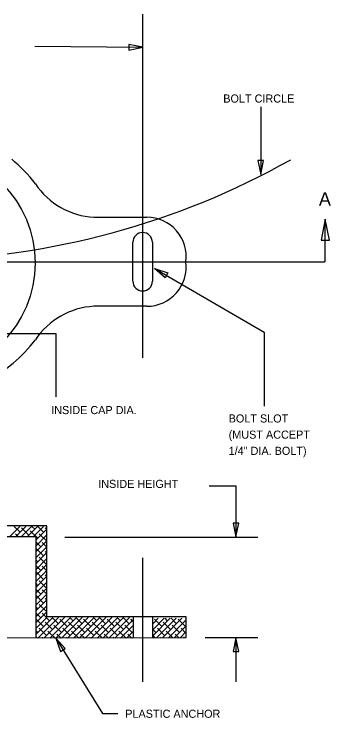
# Model space of a CAD drawing. Extents: x 12.4 to 19.6, y 6 to 16.1.
# Drawn here: x 16.63 to 18.97, y 10.68 to 15.9 of the extents above; entities that cross this region are included whole.
import ezdxf

# ---------------------------------------------------------------- set-up
doc = ezdxf.new("R2010")
doc.units = 0
for name, color, linetype in [('DETL-DIMS', 7, 'Continuous'), ('DETL-LINE', 7, 'Continuous'), ('DETL-NOTE', 7, 'Continuous'), ('DETL-PATT', 7, 'Continuous')]:
    doc.layers.add(name, color=color, linetype=linetype)

msp = doc.modelspace()

# ---------------------------------------------------------------- linework, layer by layer
at = {"layer": 'DETL-DIMS'}
for p, q in [((17.5789, 13.3479), (17.5789, 15.8959)), ((16.7799, 15.6569), (17.5759, 15.6499)), ((18.4529, 15.2089), (18.4529, 14.7269)), ((17.6869, 13.9969), (18.4779, 13.5379)), ((16.9369, 13.5269), (16.0979, 13.5269)), ((16.9369, 13.0579), (16.9369, 13.5269)), ((18.4779, 13.5379), (18.4779, 12.9899)), ((18.0699, 12.3989), (18.2669, 12.3989)), ((18.2669, 12.3989), (18.2669, 12.0199)), ((17.0019, 12.0199), (18.4299, 12.0199)), ((17.5769, 11.8669), (17.5769, 10.9479)), ((16.9339, 11.2709), (17.2801, 10.7133)), ((18.0419, 11.2749), (18.4299, 11.2749)), ((18.2669, 11.2749), (18.2669, 10.9479)), ((17.2801, 10.7133), (17.3931, 10.7133))]:
    msp.add_line(p, q, dxfattribs=at)
for points in [[(17.5789, 15.6499), (17.4749, 15.6699), (17.4749, 15.6289)], [(18.4519, 14.7079), (18.4729, 14.8109), (18.4309, 14.8109)], [(18.9289, 14.3759), (18.8989, 14.2209), (18.9609, 14.2209)], [(17.6659, 14.0099), (17.7649, 13.9769), (17.7449, 13.9409)], [(18.2689, 12.0209), (18.2899, 12.1239), (18.2489, 12.1239)], [(16.9339, 11.2709), (16.9699, 11.1723), (17.0051, 11.1935)], [(18.2679, 11.2739), (18.2479, 11.1709), (18.2889, 11.1709)]]:
    msp.add_lwpolyline(points, close=True, dxfattribs=at)
for points in [[(18.9289, 14.0599), (18.9289, 14.3759)], [(12.9759, 14.0599), (18.9259, 14.0599)]]:
    msp.add_lwpolyline(points, dxfattribs=at)
msp.add_arc((15.8374, 19.8541), 5.7813, 243.01004, 299.38525, dxfattribs=at)
at = {"layer": 'DETL-LINE'}
for points in [[(17.2169, 14.3899), (17.6089, 14.3899)], [(17.5059, 14.0599), (17.5059, 14.2049)], [(17.6499, 14.2049), (17.6499, 14.0599), (17.6499, 13.9159)], [(17.5059, 13.9159), (17.5059, 14.0599)], [(17.6089, 13.7299), (17.2169, 13.7299)], [(16.2019, 11.2739), (17.8999, 11.2749), (17.8999, 11.4279), (16.8679, 11.4279), (16.8679, 12.1019), (15.0529, 12.1019), (15.0529, 11.4179), (13.9819, 11.4179), (13.9809, 11.2729)], [(15.1359, 11.2799), (15.1359, 12.0229), (16.7859, 12.0229), (16.7859, 11.2799)], [(17.5079, 11.4279), (17.5079, 11.2749)], [(17.6519, 11.4279), (17.6519, 11.2749)]]:
    msp.add_lwpolyline(points, dxfattribs=at)
msp.add_circle((15.952, 14.0508), 0.83, dxfattribs=at)
for centre, radius, start, end in [((15.9586, 14.0188), 1.0313, 36.8699, 50.9692), ((17.248, 14.9475), 0.5583, 213.721, 266.7892), ((17.6086, 14.0987), 0.2913, 352.3718, 90), ((17.5776, 14.2044), 0.0722, 0, 180), ((17.6086, 14.0214), 0.2913, 270, 7.6282), ((17.5776, 13.9157), 0.0722, 180, 0), ((17.248, 13.1726), 0.5583, 93.2108, 146.279), ((15.9586, 14.1013), 1.0313, 270, 323.1301)]:
    msp.add_arc(centre, radius, start, end, dxfattribs=at)
at = {"layer": 'DETL-PATT'}
for p, q in [((16.5889, 12.0189), (16.6679, 12.0989)), ((16.6699, 12.0559), (16.6269, 12.0989)), ((16.6329, 12.0189), (16.7119, 12.0989)), ((16.6769, 12.0189), (16.7559, 12.0989)), ((16.7349, 12.0339), (16.6799, 12.0889)), ((16.7199, 12.0189), (16.7999, 12.0989)), ((16.8009, 12.0119), (16.7459, 12.0669)), ((16.7789, 12.0779), (16.7579, 12.0989)), ((16.7639, 12.0189), (16.8439, 12.0989)), ((16.7859, 11.9969), (16.8649, 12.0769)), ((16.8439, 12.0559), (16.8019, 12.0989)), ((16.8649, 12.0789), (16.8549, 12.0889)), ((16.6619, 12.0189), (16.6369, 12.0449)), ((16.7059, 12.0189), (16.7019, 12.0229)), ((16.7859, 11.9529), (16.8649, 12.0329)), ((16.8649, 11.9919), (16.8119, 12.0449)), ((16.7859, 11.9099), (16.8649, 11.9889)), ((16.8229, 11.9469), (16.7859, 11.9839)), ((16.8649, 11.9479), (16.8339, 11.9799)), ((16.7859, 11.8659), (16.8649, 11.9449)), ((16.7859, 11.8219), (16.8649, 11.9019)), ((16.8439, 11.8809), (16.7899, 11.9359)), ((16.8649, 11.9039), (16.8549, 11.9139)), ((16.7859, 11.7779), (16.8649, 11.8579)), ((16.8009, 11.8369), (16.7859, 11.8519)), ((16.8649, 11.8169), (16.8119, 11.8699)), ((16.7859, 11.7349), (16.8649, 11.8139)), ((16.8229, 11.7719), (16.7859, 11.8089)), ((16.8649, 11.7729), (16.8339, 11.8049)), ((16.7859, 11.6909), (16.8649, 11.7699)), ((16.8439, 11.7059), (16.7899, 11.7609)), ((16.8649, 11.7289), (16.8549, 11.7389)), ((16.7859, 11.6469), (16.8649, 11.7269)), ((16.8649, 11.6419), (16.8119, 11.6949)), ((16.7859, 11.6029), (16.8649, 11.6829)), ((16.8009, 11.6619), (16.7859, 11.6769)), ((16.7859, 11.5599), (16.8649, 11.6389)), ((16.8229, 11.5969), (16.7859, 11.6339)), ((16.7859, 11.5159), (16.8649, 11.5949)), ((16.8439, 11.5309), (16.7899, 11.5859)), ((16.8649, 11.5979), (16.8339, 11.6299)), ((16.7859, 11.4719), (16.8649, 11.5519)), ((16.8649, 11.5539), (16.8549, 11.5639)), ((16.7859, 11.4279), (16.8649, 11.5079)), ((16.8009, 11.4869), (16.7859, 11.5019)), ((16.8649, 11.4669), (16.8119, 11.5199)), ((16.7859, 11.3849), (16.8649, 11.4639)), ((16.8229, 11.4219), (16.7859, 11.4589)), ((16.8879, 11.3999), (16.8339, 11.4549)), ((16.7859, 11.3409), (16.8689, 11.4239)), ((16.7859, 11.2969), (16.9119, 11.4239)), ((16.8439, 11.3559), (16.7899, 11.4109)), ((16.8029, 11.2709), (16.9559, 11.4239)), ((16.8469, 11.2709), (16.9999, 11.4239)), ((16.9099, 11.3339), (16.8549, 11.3889)), ((16.8899, 11.2709), (17.0439, 11.4239)), ((16.9539, 11.3779), (16.9079, 11.4239)), ((16.9339, 11.2709), (17.0869, 11.4239)), ((17.0189, 11.3559), (16.9649, 11.4109)), ((16.9779, 11.2709), (17.1309, 11.4239)), ((16.9979, 11.4219), (16.9949, 11.4239)), ((17.0219, 11.2709), (17.1749, 11.4239)), ((17.0849, 11.3339), (17.0299, 11.3889)), ((17.0629, 11.3999), (17.0389, 11.4239)), ((17.0649, 11.2709), (17.2189, 11.4239)), ((17.1289, 11.3779), (17.0829, 11.4239)), ((17.1089, 11.2709), (17.2619, 11.4239)), ((17.1939, 11.3559), (17.1399, 11.4109)), ((17.1529, 11.2709), (17.3059, 11.4239)), ((17.1729, 11.4219), (17.1699, 11.4239)), ((17.1969, 11.2709), (17.3499, 11.4239)), ((17.2599, 11.3339), (17.2049, 11.3889)), ((17.2379, 11.3999), (17.2139, 11.4239)), ((17.2399, 11.2709), (17.3939, 11.4239)), ((17.3039, 11.3779), (17.2579, 11.4239)), ((17.2839, 11.2709), (17.4369, 11.4239)), ((17.3699, 11.3559), (17.3149, 11.4109)), ((17.3279, 11.2709), (17.4809, 11.4239)), ((17.3479, 11.4219), (17.3449, 11.4239)), ((17.3719, 11.2709), (17.5049, 11.4049)), ((17.4349, 11.3339), (17.3799, 11.3889)), ((17.4129, 11.3999), (17.3889, 11.4239)), ((17.4789, 11.3779), (17.4329, 11.4239)), ((17.5049, 11.3949), (17.4899, 11.4109)), ((17.6529, 11.2889), (17.7819, 11.4179)), ((17.6529, 11.3329), (17.7379, 11.4179)), ((17.6529, 11.3769), (17.6939, 11.4179)), ((17.6539, 11.3779), (17.6529, 11.3789)), ((17.7189, 11.3559), (17.6649, 11.4109)), ((17.6839, 11.2759), (17.8249, 11.4179)), ((17.7269, 11.2759), (17.8689, 11.4179)), ((17.7849, 11.3339), (17.7299, 11.3889)), ((17.7629, 11.3999), (17.7449, 11.4179)), ((17.7709, 11.2759), (17.8959, 11.4019)), ((17.8289, 11.3779), (17.7889, 11.4179)), ((17.8949, 11.3559), (17.8399, 11.4109)), ((16.8009, 11.3119), (16.7859, 11.3279)), ((16.8659, 11.2899), (16.8119, 11.3449)), ((16.9299, 11.2709), (16.8769, 11.3229)), ((16.9759, 11.3119), (16.9209, 11.3669)), ((17.0409, 11.2899), (16.9869, 11.3449)), ((17.1049, 11.2709), (17.0519, 11.3229)), ((17.1509, 11.3119), (17.0959, 11.3669)), ((17.2159, 11.2899), (17.1619, 11.3449)), ((17.2799, 11.2709), (17.2269, 11.3229)), ((17.3259, 11.3119), (17.2709, 11.3669)), ((17.3909, 11.2899), (17.3369, 11.3449)), ((17.4549, 11.2709), (17.4019, 11.3229)), ((17.4149, 11.2709), (17.5049, 11.3609)), ((17.5009, 11.3119), (17.4459, 11.3669)), ((17.6759, 11.3119), (17.6529, 11.3349)), ((17.7409, 11.2899), (17.6869, 11.3449)), ((17.7989, 11.2759), (17.7519, 11.3229)), ((17.8509, 11.3119), (17.7959, 11.3669)), ((17.8149, 11.2759), (17.8959, 11.3579)), ((17.8959, 11.3099), (17.8619, 11.3449)), ((16.7989, 11.2709), (16.7859, 11.2839)), ((16.8419, 11.2709), (16.8339, 11.2789)), ((16.9739, 11.2709), (16.9429, 11.3009)), ((17.0169, 11.2709), (17.0089, 11.2789)), ((17.1489, 11.2709), (17.1179, 11.3009)), ((17.1919, 11.2709), (17.1839, 11.2789)), ((17.3239, 11.2709), (17.2929, 11.3009)), ((17.3669, 11.2709), (17.3589, 11.2789)), ((17.4589, 11.2709), (17.5049, 11.3169)), ((17.4989, 11.2709), (17.4679, 11.3009)), ((17.5029, 11.2709), (17.5049, 11.2729)), ((17.6679, 11.2759), (17.6529, 11.2919)), ((17.7119, 11.2759), (17.7089, 11.2789)), ((17.8429, 11.2759), (17.8179, 11.3009)), ((17.8589, 11.2759), (17.8959, 11.3139)), ((17.8869, 11.2759), (17.8839, 11.2789))]:
    msp.add_line(p, q, dxfattribs=at)

# ---------------------------------------------------------------- texts
at = {"layer": 'DETL-NOTE'}
for s, height, p in [('BOLT CIRCLE', 0.06, (18.1749, 15.2399)), ('A', 0.1, (18.8829, 14.4759)), ('INSIDE CAP DIA.', 0.06, (16.9009, 12.9309)), ('BOLT SLOT', 0.06, (18.2148, 12.8689)), ('(MUST ACCEPT  ', 0.06, (18.2148, 12.7489)), ('1/4" DIA. BOLT)', 0.06, (18.2148, 12.6289)), ('INSIDE HEIGHT', 0.06, (17.2489, 12.3839)), ('PLASTIC ANCHOR', 0.06, (17.449, 10.6802))]:
    msp.add_text(s, height=height, dxfattribs=at).set_placement(p)

doc.saveas('drawing.dxf')
